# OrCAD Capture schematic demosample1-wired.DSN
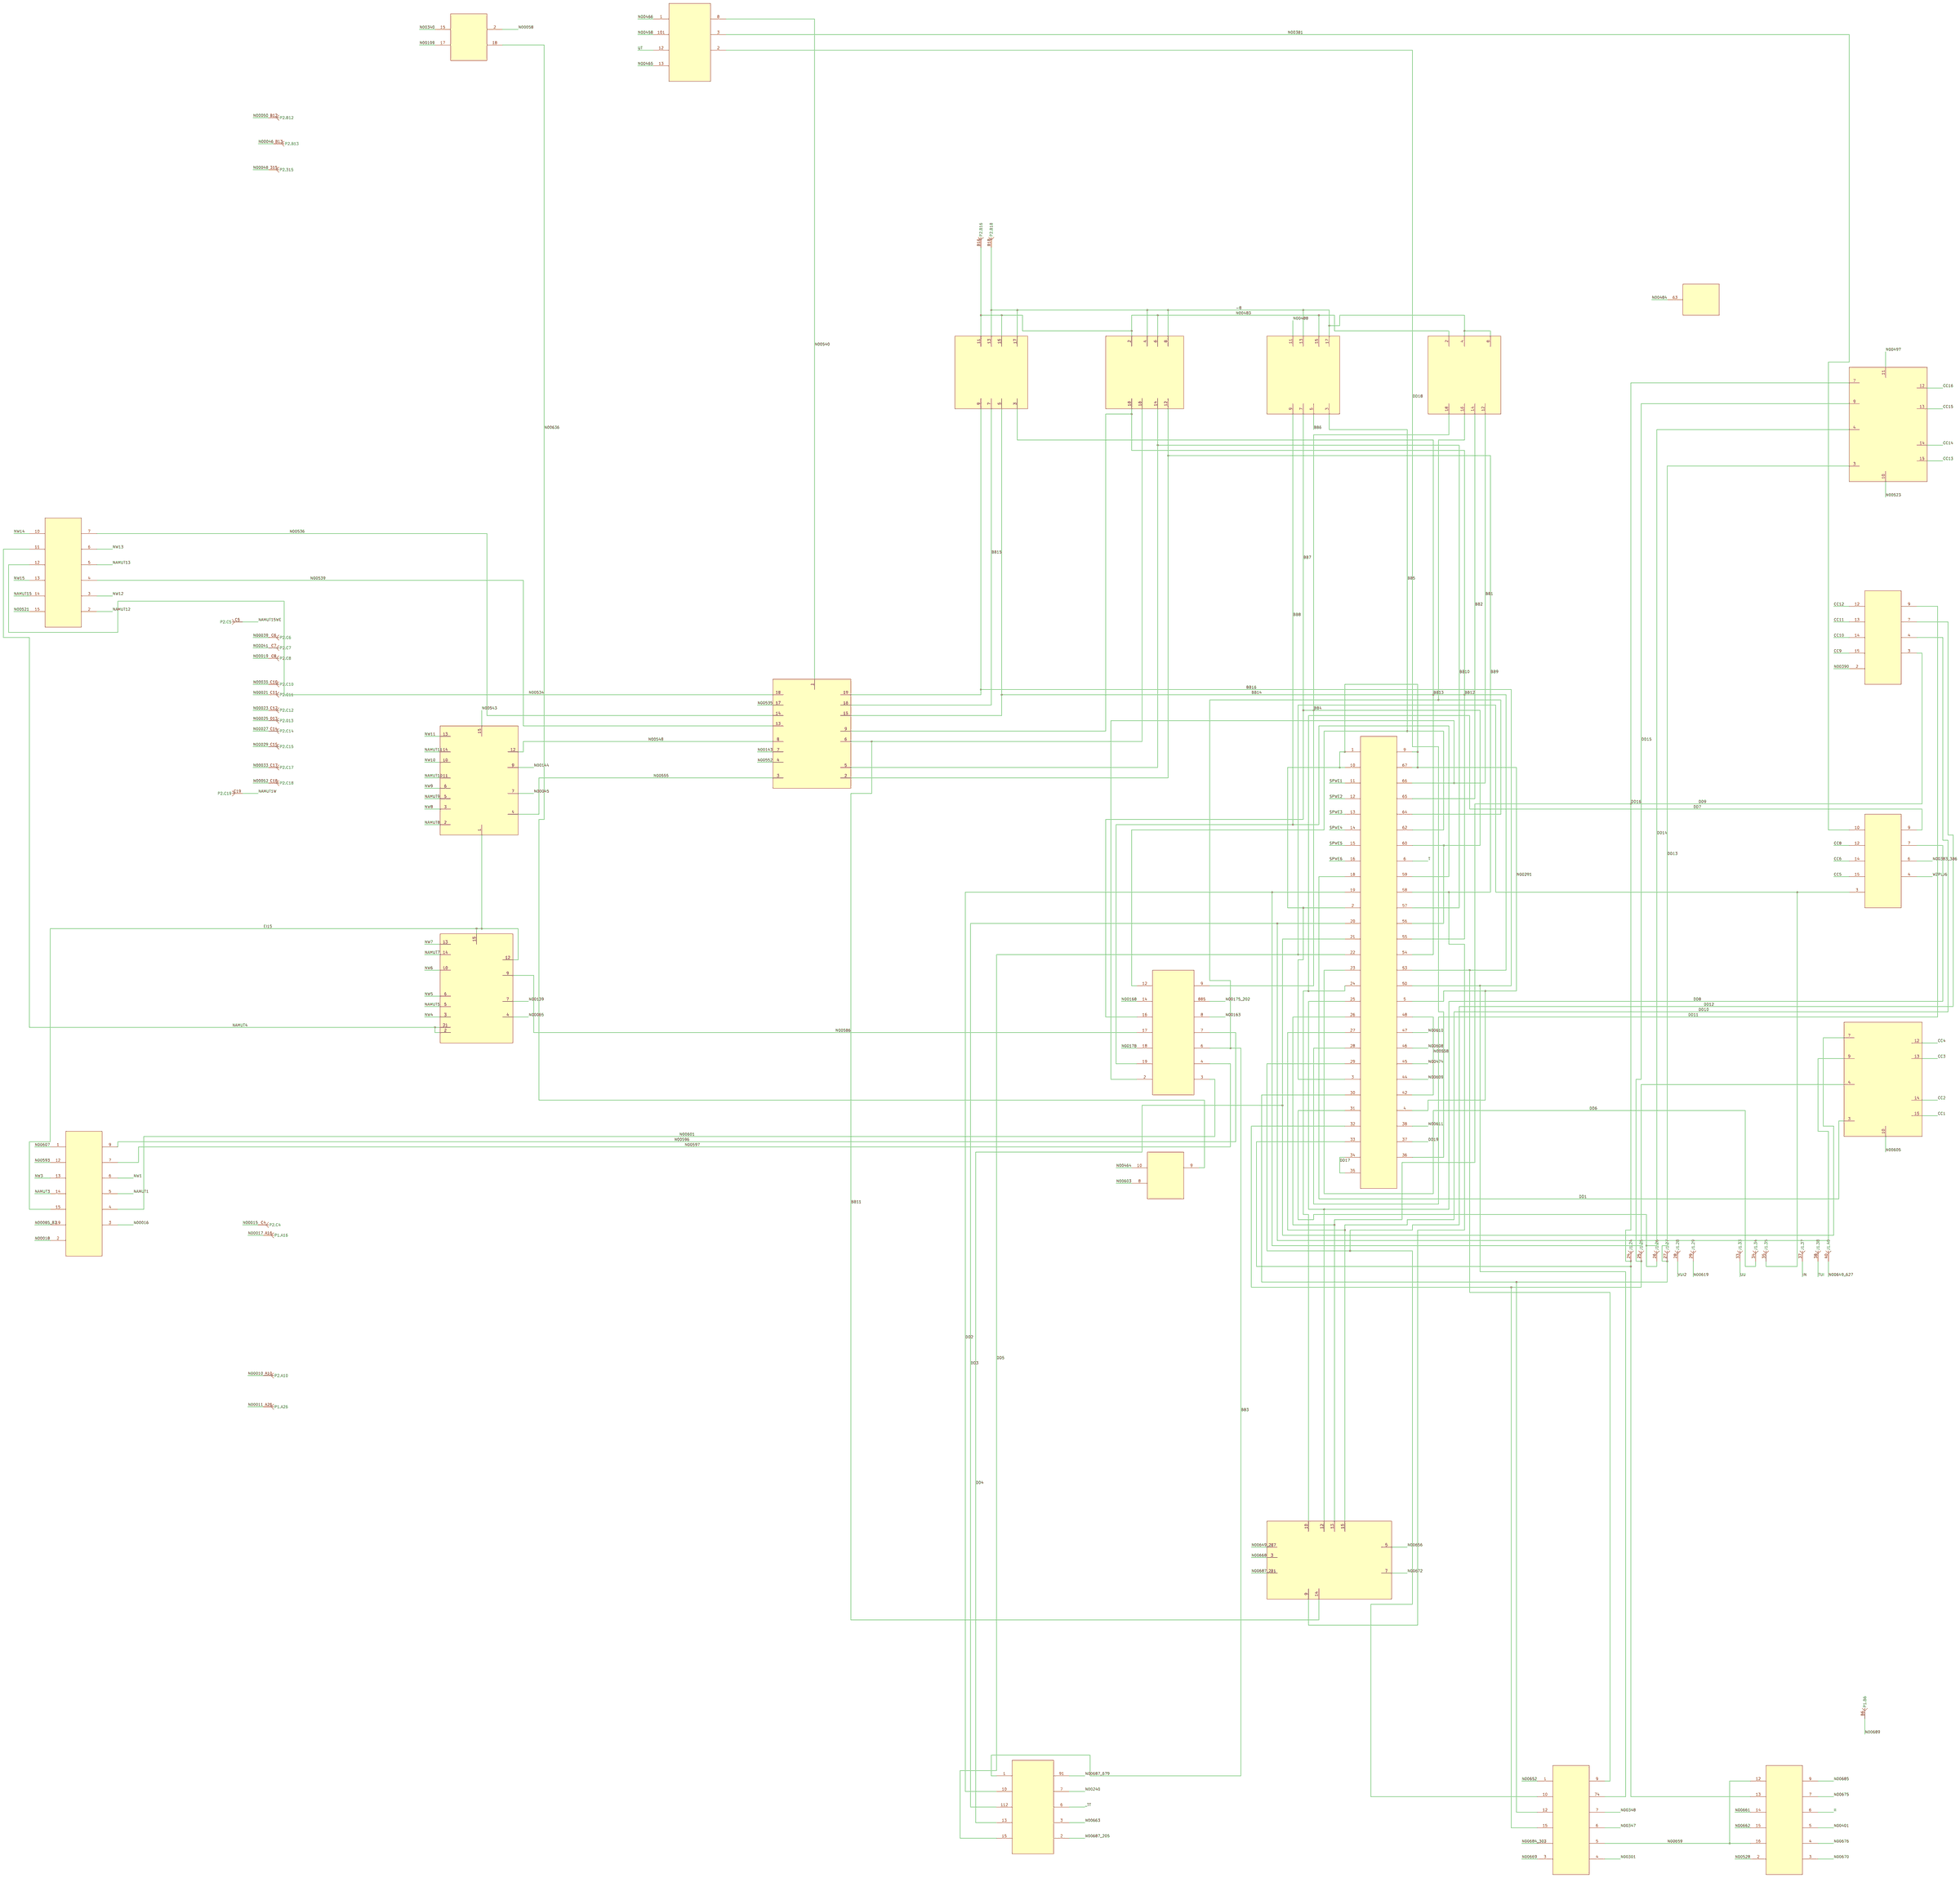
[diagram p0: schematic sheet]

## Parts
J1  CONNECTOR
P1  CONNECTOR
P2  CONNECTOR
R5  1K00
U9  74F244
U10  74F244
U11  74F374
U12  74F374
U13  74F257
U14  74F257
U15  74F257
U16  74F257
U43  IDT7210L
U59  74LS85
U61  74LS85
U62  74LS298
U64  74LS298
U65  74LS85
U71  74F08
U73  74LS298
U74  74LS298
U85  74F240
U88  74F32
U90  74LS85

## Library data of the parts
J1 = OBS_J1
P1 = OBS_P1
P2 = OBS_P2
R5 = OBS_R5
U9 = OBS_U9
U10 = OBS_U10
U11 = OBS_U11
U12 = OBS_U12
U13 = OBS_U13
U14 = OBS_U14
U15 = OBS_U15
U16 = OBS_U16
U43 = OBS_U43
U59 = OBS_U59
U61 = OBS_U61
U62 = OBS_U62
U64 = OBS_U64
U65 = OBS_U65
U71 = OBS_U71
U73 = OBS_U73
U74 = OBS_U74
U85 = OBS_U85
U88 = OBS_U88
U90 = OBS_U90

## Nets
-8: P2.B18(P2.B18) U9.4 U9.8 U9.13 U9.17 U10.4 U10.8 U10.13 U10.17
_TT: U61.6
BB1: U9.12 U12.2 U43.66
BB2: U9.14 U43.65
BB3: U9.16 U12.6 U43.64 U61.1
BB4: U9.18 U12.9
BB5: U9.3 U12.12 U43.62
BB6: U9.5
BB7: U9.7 U12.16 U43.56 U43.60
BB8: U9.9 U12.19 U43.59
BB9: U10.12 U11.2 U43.58 U65.9
BB10: U10.14 U11.5 U43.57
BB11: U10.16 U11.6 U65.14
BB12: U10.18 U11.9 U43.55
BB13: U10.3 U43.54
BB14: U10.5 U11.15 U43.53 U59.9
BB15: U10.7 U11.16
BB16: U10.9 U11.19 U43.50 U59.74
CC1: U62.15
CC2: U62.14
CC3: U62.13
CC4: U62.12
CC5: U64.15
CC6: U64.14
CC8: U64.12
CC9: U74.15
CC10: U74.14
CC11: U74.13
CC12: U74.12
CC13: U73.15
CC14: U73.14
CC15: U73.13
CC16: U73.12
DD1: U43.18 U62.3
DD2: U43.19 U61.10 U62.4
DD3: U43.20 U61.112 U62.9
DD4: U43.21 U61.13 U62.7
DD5: J1.35(J1.35) U43.22 U61.15 U64.3
DD6: J1.34(J1.34) U43.23
DD7: U43.24 U64.9 U65.10
DD8: U43.25 U64.7 U65.12
DD9: U43.26 U65.13 U74.3
DD10: U43.27 U65.15 U74.4
DD11: U43.28 U74.9
DD12: U43.29 U59.10 U74.7
DD13: J1.27(J1.27) U43.30 U59.12 U73.3
DD14: J1.26(J1.26) U43.31 U73.4
DD15: J1.25(J1.25) U43.32 U59.15 U73.9
DD16: J1.24(J1.24) U43.33 U73.7 U90.13
DD17: U43.34 U43.35
DD18: U43.36 U88.2
DD19: U43.37
EI15: U13.12 U13.15 U14.1 U16.15
II: U90.6
IN: J1.37(J1.37)
N00085_82: U16.19
N00175_202: U12.885
N00383_386: U64.6
N00649_237: U65.4
N00649_627: J1.40(J1.40)
N00684_303: U59.2
N00687_205: U61.2
N00687_241: U65.2
N00687_679: U61.91
NAMUT1: U16.5
NAMUT1W: P2.C19(P2.C19)
NAMUT3: U16.14
NAMUT4: U13.2 U13.21 U15.11
NAMUT5: U13.5
NAMUT7: U13.14
NAMUT8: U14.2
NAMUT9: U14.5
NAMUT10: U14.11
NAMUT11: U14.14
NAMUT12: U15.2
NAMUT13: U15.5
NAMUT15: U15.14
NAMUT15WE: P2.C5(P2.C5)
NW1: U16.6
NW3: U16.13
NW4: U13.3
NW5: U13.6
NW6: U13.10
NW7: U13.13
NW8: U14.3
NW9: U14.6
NW10: U14.10
NW11: U14.13
NW12: U15.3
NW13: U15.6
NW14: U15.10
NW15: U15.13
SPWE1: U43.11
SPWE2: U43.12
SPWE3: U43.13
SPWE4: U43.14
SPWE5: U43.15
SPWE6: U43.16
T: U43.6
TUI: J1.38(J1.38)
UT: U88.12
UU: J1.33(J1.33)
VUI2: J1.28(J1.28)
WZPLJ6: U64.4
N00291: U43.1 U43.2 U43.3 U43.4 U43.5 U43.9 U43.10 U43.67
N00381: U64.10 U88.3
N00483: P2.B16(P2.B16) U9.2 U9.15 U10.2 U10.6 U10.11 U10.15
N00534: U11.18 U15.12
N00536: U11.14 U15.7
N00539: U11.13 U15.4
N00540: U11.1 U88.8
N00548: U11.8 U14.12
N00555: U11.3 U14.4
N00558: U43.42 U43.48
N00586: U12.17 U13.9
N00596: U12.7 U16.9
N00597: U12.4 U16.7
N00601: U12.3 U16.4
N00636: U71.9 U85.18
N00659: U59.5 U90.12 U90.16

Not connected (* = marked no-connect by the designer): J1 29(J1.29); P1 A16(P1.A16) A26(P1.A26) B6(P1.B6); P2 013(P2.013) 315(P2.315) A10(P2.A10) B12(P2.B12) B13(P2.B13) C4(P2.C4) C6(P2.C6) C7(P2.C7) C8(P2.C8) C10(P2.C10) C11(P2.C11) C12(P2.C12) C14(P2.C14) C15(P2.C15) C17(P2.C17) C18(P2.C18); R5 63; U9 11; U11 4 7 17; U12 8 14 18; U13 4 7; U14 7 9 15; U15 15; U16 1 2 3 12; U43 38 44 45 46 47; U59 1 3 4 6 7; U61 3 7; U62 10; U65 3 5 7; U71 8 10; U73 10 11; U74 2; U85 2 15 17; U88 1 13 101; U90 2 3 4 5 7 9 14 15
